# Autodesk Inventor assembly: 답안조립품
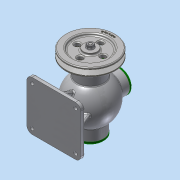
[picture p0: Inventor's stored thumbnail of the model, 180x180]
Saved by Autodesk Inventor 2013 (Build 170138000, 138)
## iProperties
Created: 2018-06
Part Number: 답안조립품
Document SubType Name: Assembly
Designer: Administrator
Author: Administrator
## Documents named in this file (19)
- C:\Users\Administrator\Desktop\480612V1010\답안조립품.iam
- C:\Users\Administrator\Desktop\480612V1010\본체.ipt
- C:\Users\Administrator\Desktop\480612V1010\V-벨트풀리.ipt
- C:\Users\Administrator\Desktop\480612V1010\너트 M8.ipt
- C:\Users\Administrator\Desktop\480612V1010\뒤커버.ipt
- C:\Users\Administrator\Desktop\480612V1010\멈춤링 15x1.ipt
- C:\Users\Administrator\Desktop\480612V1010\멈춤링 35x1.6.ipt
- 멈춤링 35x1.6.ipt
- C:\Users\Administrator\Desktop\480612V1010\베어링 6202.ipt
- 베어링 6202.ipt
- C:\Users\Administrator\Desktop\480612V1010\볼트 M4x12.ipt
- C:\Users\Administrator\Desktop\480612V1010\볼트 M4x16.ipt
- C:\Users\Administrator\Desktop\480612V1010\부시.ipt
- C:\Users\Administrator\Desktop\480612V1010\상부커버.ipt
- C:\Users\Administrator\Desktop\480612V1010\슬라이드.ipt
- C:\Users\Administrator\Desktop\480612V1010\앞커버.ipt
- C:\Users\Administrator\Desktop\480612V1010\오일 실 15 30 7.ipt
- C:\Users\Administrator\Desktop\480612V1010\키 4x4x12.ipt
- C:\Users\Administrator\Desktop\480612V1010\편심축.ipt
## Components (1 placed, 1 different names)
1. V-벨트풀리:1
